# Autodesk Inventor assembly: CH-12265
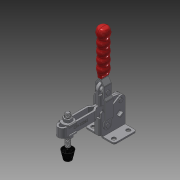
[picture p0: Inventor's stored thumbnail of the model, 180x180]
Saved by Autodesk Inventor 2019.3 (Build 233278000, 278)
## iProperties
Company: Î¢ÈíÖÐ¹ú
Created: 2012-09
Part Number: CH-12265
Material: Ogólny
Description: STEP AP203
Document SubType Name: Assembly
Designer: CADENGINEERING4
Stock Number: DOCISK PIONOWY
Sending System: SolidWorks 2010
Preprocessor: SwSTEP 2.0
Title: CH-12265.STEP
Author: Î¢ÈíÓÃ»§
Revision Number: ÈÎºÎ
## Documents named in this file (13)
- D:\Vault_2016\Projekty\Clamptek\STRONA\Vertical toggle clamp\CH-12265\CH-12265.iam
- D:\Vault_2016\Projekty\Clamptek\STRONA\Vertical toggle clamp\CH-12265\CH-FC-38312 Nut.ipt
- D:\Vault_2016\Projekty\Clamptek\STRONA\Vertical toggle clamp\CH-12265\CH-12265-03 STRAIGHT HANDLE.ipt
- D:\Vault_2016\Projekty\Clamptek\STRONA\Vertical toggle clamp\CH-12265\CH-12265-05.ipt
- D:\Vault_2016\Projekty\Clamptek\STRONA\Vertical toggle clamp\CH-12265\CH-12265-08.ipt
- D:\Vault_2016\Projekty\Clamptek\STRONA\Vertical toggle clamp\CH-12265\CH-FW-380.ipt
- D:\Vault_2016\Projekty\Clamptek\STRONA\Vertical toggle clamp\CH-12265\CH-12265-07.ipt
- D:\Vault_2016\Projekty\Clamptek\STRONA\Vertical toggle clamp\CH-12265\CH-12265-01 FLANGED BASE.ipt
- D:\Vault_2016\Projekty\Clamptek\STRONA\Vertical toggle clamp\CH-12265\CH-12265-06.ipt
- D:\Vault_2016\Projekty\Clamptek\STRONA\Vertical toggle clamp\CH-12265\CH-12265-02 U-BAR.ipt
- D:\Vault_2016\Projekty\Clamptek\STRONA\Vertical toggle clamp\CH-12265\CH-12265-04 CONNECTING-PLATE.ipt
- D:\Vault_2016\Projekty\Clamptek\STRONA\Vertical toggle clamp\CH-12265\CH-FC-38312 SPINDLE SUPPLIED.ipt
- D:\Vault_2016\Projekty\Clamptek\STRONA\Vertical toggle clamp\CH-12265\CH-12265-09.ipt
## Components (18 placed, 18 different names)
1. CH-FC-38312 Nut_1 — Zestawiające:30, Zestawiające:31
2. CH-12265-03 STRAIGHT HANDLE_2 — Zestawiające:8, Zestawiające:9, Zestawiające:10, Zestawiające:11, Zestawiające:13, Zestawiające:14, Zestawiające:20, Zestawiające:21, Zestawiające:22
3. CH-12265-05_3 — Zestawiające:4
4. CH-12265-08_4 — Zestawiające:17, Zestawiające:18, Zestawiające:19
5. CH-FW-380_5 — Zestawiające:24, Zestawiające:26, Kątowe:2, Zestawiające:29, Zestawiające:32, Równoległe:4
6. CH-12265-05_6 — Równoległe:1, Zestawiające:1, Zestawiające:2
7. CH-12265-08_7 — Zestawiające:15, Zestawiające:16
8. CH-12265-07_8 — Zestawiające:20, Zestawiające:21, Zestawiające:22
9. CH-12265-01 FLANGED BASE_9 — Zestawiające:4, Zestawiające:5, Równoległe:3, Zestawiające:7, Zestawiające:8, Zestawiające:17, Zestawiające:18
10. CH-12265-06_10 — Równoległe:3, Zestawiające:7, Zestawiające:9
11. CH-FC-38312 Nut_11 — Zestawiające:29, Zestawiające:32, Zestawiające:33
12. CH-12265-02 U-BAR_12 — Równoległe:1, Zestawiające:1, Zestawiające:3, Zestawiające:5, Zestawiające:19, Zestawiające:23, Zestawiające:24, Zestawiające:25, Zestawiające:27, Zestawiające:28, Kątowe:1, Kątowe:2
13. CH-12265-04 CONNECTING-PLATE_13 — Zestawiające:2, Zestawiające:3, Równoległe:2, Zestawiające:6, Zestawiające:15, Zestawiające:16, Zestawiające:23
14. CH-FC-38312 SPINDLE SUPPLIED_14 — Zestawiające:33, Równoległe:4
15. CH-12265-06_15 — Równoległe:2, Zestawiające:6, Zestawiające:10, Zestawiające:12
16. CH-12265-09_16 — Zestawiające:13, Zestawiające:14
17. CH-FW-380_17 — Zestawiające:25, Zestawiające:26, Zestawiające:27, Zestawiające:28, Kątowe:1, Zestawiające:30, Zestawiające:31
18. CH-12265-09_18 — Zestawiające:11, Zestawiające:12
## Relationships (39: Mate 33, Flush 4, Angle 2)
- Równoległe:1 [Flush]: CH-12265-05_6 ↔ CH-12265-02 U-BAR_12
- Zestawiające:1 [Mate]: CH-12265-05_6 ↔ CH-12265-02 U-BAR_12
- Zestawiające:2 [Mate]: CH-12265-05_6 ↔ CH-12265-04 CONNECTING-PLATE_13
- Zestawiające:3 [Mate]: CH-12265-02 U-BAR_12 ↔ CH-12265-04 CONNECTING-PLATE_13
- Zestawiające:4 [Mate]: CH-12265-05_3 ↔ CH-12265-01 FLANGED BASE_9
- Zestawiające:5 [Mate]: CH-12265-01 FLANGED BASE_9 ↔ CH-12265-02 U-BAR_12
- Równoległe:2 [Flush]: CH-12265-04 CONNECTING-PLATE_13 ↔ CH-12265-06_15
- Zestawiające:6 [Mate]: CH-12265-04 CONNECTING-PLATE_13 ↔ CH-12265-06_15
- Równoległe:3 [Flush]: CH-12265-01 FLANGED BASE_9 ↔ CH-12265-06_10
- Zestawiające:7 [Mate]: CH-12265-01 FLANGED BASE_9 ↔ CH-12265-06_10
- Zestawiające:8 [Mate]: CH-12265-03 STRAIGHT HANDLE_2 ↔ CH-12265-01 FLANGED BASE_9
- Zestawiające:9 [Mate]: CH-12265-03 STRAIGHT HANDLE_2 ↔ CH-12265-06_10
- Zestawiające:10 [Mate]: CH-12265-03 STRAIGHT HANDLE_2 ↔ CH-12265-06_15
- Zestawiające:11 [Mate]: CH-12265-03 STRAIGHT HANDLE_2 ↔ CH-12265-09_18
- Zestawiające:12 [Mate]: CH-12265-06_15 ↔ CH-12265-09_18
- Zestawiające:13 [Mate]: CH-12265-03 STRAIGHT HANDLE_2 ↔ CH-12265-09_16
- Zestawiające:14 [Mate]: CH-12265-03 STRAIGHT HANDLE_2 ↔ CH-12265-09_16
- Zestawiające:15 [Mate]: CH-12265-08_7 ↔ CH-12265-04 CONNECTING-PLATE_13
- Zestawiające:16 [Mate]: CH-12265-08_7 ↔ CH-12265-04 CONNECTING-PLATE_13
- Zestawiające:17 [Mate]: CH-12265-08_4 ↔ CH-12265-01 FLANGED BASE_9
- Zestawiające:18 [Mate]: CH-12265-08_4 ↔ CH-12265-01 FLANGED BASE_9
- Zestawiające:19 [Mate]: CH-12265-08_4 ↔ CH-12265-02 U-BAR_12
- Zestawiające:20 [Mate]: CH-12265-03 STRAIGHT HANDLE_2 ↔ CH-12265-07_8
- Zestawiające:21 [Mate]: CH-12265-03 STRAIGHT HANDLE_2 ↔ CH-12265-07_8
- Zestawiające:22 [Mate]: CH-12265-03 STRAIGHT HANDLE_2 ↔ CH-12265-07_8
- Zestawiające:23 [Mate]: CH-12265-02 U-BAR_12 ↔ CH-12265-04 CONNECTING-PLATE_13
- Zestawiające:24 [Mate]: CH-FW-380_5 ↔ CH-12265-02 U-BAR_12
- Zestawiające:25 [Mate]: CH-12265-02 U-BAR_12 ↔ CH-FW-380_17
- Zestawiające:26 [Mate]: CH-FW-380_5 ↔ CH-FW-380_17
- Zestawiające:27 [Mate]: CH-12265-02 U-BAR_12 ↔ CH-FW-380_17
- Zestawiające:28 [Mate]: CH-12265-02 U-BAR_12 ↔ CH-FW-380_17
- Kątowe:1 [Angle]: CH-12265-02 U-BAR_12 ↔ CH-FW-380_17
- Kątowe:2 [Angle]: CH-FW-380_5 ↔ CH-12265-02 U-BAR_12
- Zestawiające:29 [Mate]: CH-FW-380_5 ↔ CH-FC-38312 Nut_11
- Zestawiające:30 [Mate]: CH-FC-38312 Nut_1 ↔ CH-FW-380_17
- Zestawiające:31 [Mate]: CH-FC-38312 Nut_1 ↔ CH-FW-380_17
- Zestawiające:32 [Mate]: CH-FW-380_5 ↔ CH-FC-38312 Nut_11
- Zestawiające:33 [Mate]: CH-FC-38312 Nut_11 ↔ CH-FC-38312 SPINDLE SUPPLIED_14
- Równoległe:4 [Flush]: CH-FW-380_5 ↔ CH-FC-38312 SPINDLE SUPPLIED_14
